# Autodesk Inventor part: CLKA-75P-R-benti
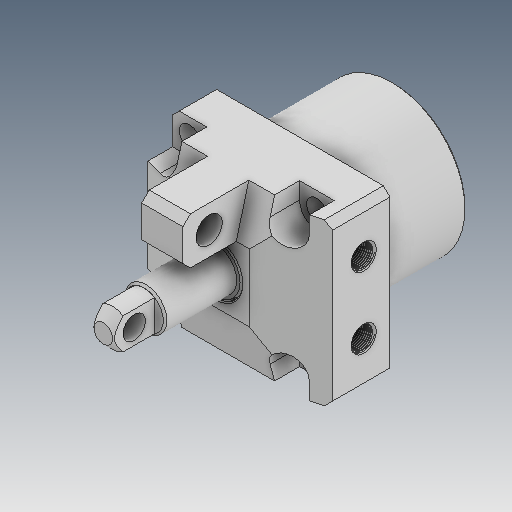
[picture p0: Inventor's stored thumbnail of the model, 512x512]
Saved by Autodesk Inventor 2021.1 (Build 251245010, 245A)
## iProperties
Created: 2018-07
Part Number: CLKA-75P-R-benti
Material: Ogólny
Document SubType Name: Modeling
Designer: user
Density: 1 g/cm^3
Appearance: Domyślna
Author: user
Revision Number: ÈÎºÎ
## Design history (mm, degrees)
feature "Í¹Ì¨-À­Éì5"
node "Bryła1"
